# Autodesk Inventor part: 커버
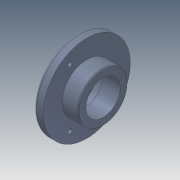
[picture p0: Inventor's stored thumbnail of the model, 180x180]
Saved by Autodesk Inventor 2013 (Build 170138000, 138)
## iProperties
Company: 한국ATC센터
Created: 2014-10
Part Number: 커버
Document SubType Name: Modeling
Designer: 한국ATC센터
Density: 2.71 g/cm^3
Material: 알루미늄 6061
Mass: 189.969 g
Surface Area: 197.235 cm^2
Volume: 70.0991 cm^3
Author: KYOUNG IL JANG
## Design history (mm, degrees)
sketch "스케치1"
  geometry: L1 (-13.5, 0)-(13.5, 0); L2 (-13.5, 0)-(-13.5, 45.5); L3 (-13.5, 45.5)-(-3.5, 45.5); L4 (-3.5, 45.5)-(-3.5, 26); L5 (-3.5, 26)-(13.5, 26); L6 (13.5, 26)-(13.5, 0); 2 further points
  constraints: 12 end point, 3 parallel, 2 perpendicular, 1 coincident, 1 horizontal, 1 midpoint
  dimensions: "d0" = 27 distance of L1.start L1.end; "d1" = 91 diameter of L3 L1; "d2" = 52 diameter of L5 L1; "d3" = 10 distance of L2.end L3.end
revolve "회전1" sketch "스케치1" stored, may be unused: angle "d4" = 90 deg
hole "구멍1" diameter "d7" = 36; stored, may be unused: countersink angle "d11" = 90 deg, drill point angle "d13" = 118 deg; dims "d5" = 10, "d6" = 10, "d8" = 6, "d9" = 40, "d10" = 8.3, "d12" = 8
sketch "스케치2"
  geometry: 2 further points
  constraints: 1 vertical alignment
  dimensions: "d14" = 35 distance of point (0, 0) point (0, 35)
hole "구멍2" sketch "스케치2" at (0, 35) diameter "d15" = 4.5; stored, may be unused: countersink angle "d19" = 90 deg, drill point angle "d21" = 118 deg; dims "d16" = 6, "d17" = 8, "d18" = 4.4, "d20" = 8
chamfer "모따기1" distance "d25" = 0.8; stored, may be unused: second distance "d26" = 2, angle "d27" = 30 deg
fillet "모깎기1" dims "d28" = 0.1, "d29" = 3
chamfer "모따기2" distance "d30" = 1; stored, may be unused: second distance "d31" = 2, angle "d32" = 30 deg
node "솔리드1"
pattern_circular "원형 패턴1" dims angle "d23" = 360 deg
